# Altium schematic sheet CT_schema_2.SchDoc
size 307 x 173 mm
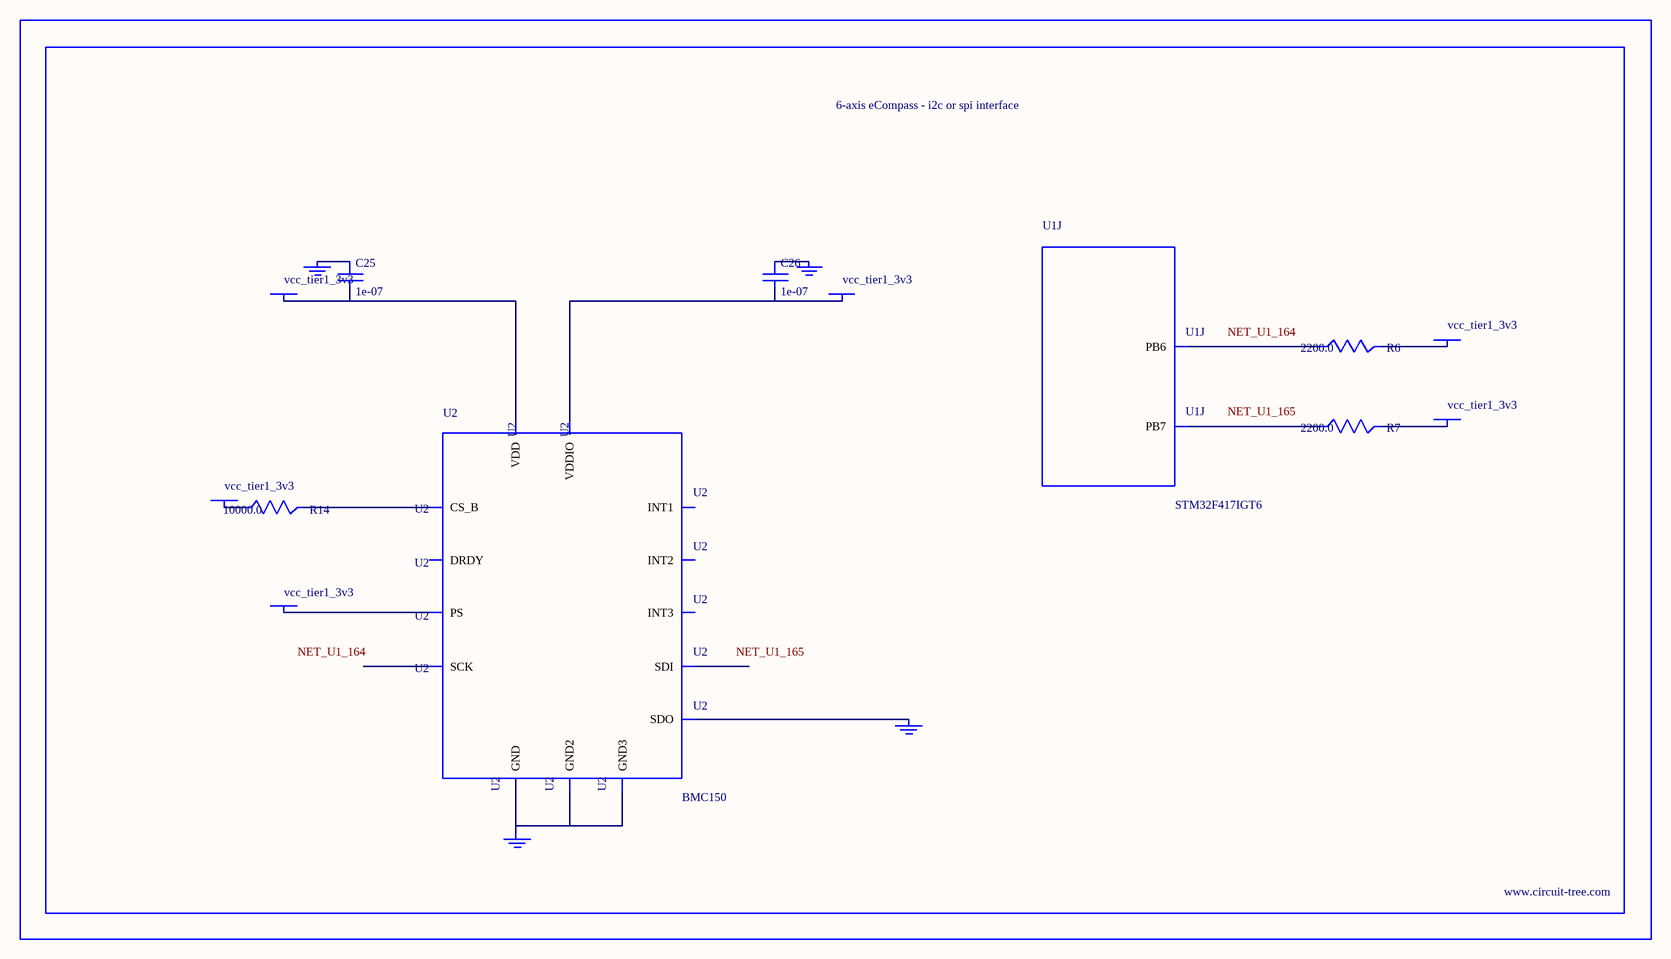
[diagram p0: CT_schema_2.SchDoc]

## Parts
BORDER1  (no value)
C25  1e-07  [C0402]
C26  1e-07  [C0402]
GND_INSTANCE_1_0  (no value)
GND_INSTANCE_1_1  (no value)
GND_INSTANCE_1_2  (no value)
GND_INSTANCE_1_3  (no value)
POWER_INSTANCE_1_0  vcc_tier1_3v3
POWER_INSTANCE_1_1  vcc_tier1_3v3
POWER_INSTANCE_1_2  vcc_tier1_3v3
POWER_INSTANCE_1_3  vcc_tier1_3v3
POWER_INSTANCE_1_4  vcc_tier1_3v3
POWER_INSTANCE_1_5  vcc_tier1_3v3
R6  2200.0  [R0603]
R7  2200.0  [R0603]
R14  10000.0  [R0603]
U1  STM32F417IGT6  [LQFP176]  (part J of 16)
U2  BMC150  [LGA14R35P5X6_200X200X100]

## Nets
NetC25_1: C25.1 GND_INSTANCE_1_1.0(GND)
NetC25_2: C25.2 POWER_INSTANCE_1_0.0(PWR) U2.8(VDD)
NetC26_1: C26.1 GND_INSTANCE_1_2.0(GND)
NetC26_2: C26.2 POWER_INSTANCE_1_1.0(PWR) U2.10(VDDIO)
NetGND_INSTANCE_1_0_0: GND_INSTANCE_1_0.0(GND) U2.1(SDO)
NetGND_INSTANCE_1_3_0: GND_INSTANCE_1_3.0(GND) U2.6(GND) U2.7(GND2) U2.9(GND3)
NetPOWER_INSTANCE_1_2_0: POWER_INSTANCE_1_2.0(PWR) R14.1
NetPOWER_INSTANCE_1_3_0: POWER_INSTANCE_1_3.0(PWR) U2.13(PS)
NetPOWER_INSTANCE_1_4_0: POWER_INSTANCE_1_4.0(PWR) R6.2
NetPOWER_INSTANCE_1_5_0: POWER_INSTANCE_1_5.0(PWR) R7.2
NetR6_1: R6.1 U1.164(PB6)
NetR7_1: R7.1 U1.165(PB7)
NetR14_2: R14.2 U2.12(CS_B)

Not connected (* = marked no-connect by the designer): U2 2(INT1) 3(INT2) 4(DRDY) 5(INT3) 11(SCK) 14(SDI)

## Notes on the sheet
- Labels drawn without touching a wire or pin: NET_U1_164, NET_U1_165

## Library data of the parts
BORDER1 = BORDER_PAGE1
C25 C26 = C0402C104K3RACTU
GND_INSTANCE_1_0-GND_INSTANCE_1_3 = GND
POWER_INSTANCE_1_0-POWER_INSTANCE_1_5 = PWR
R6 R7 = RC0603JR-072K2L
R14 = RC0603JR-0710KL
